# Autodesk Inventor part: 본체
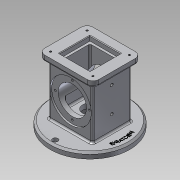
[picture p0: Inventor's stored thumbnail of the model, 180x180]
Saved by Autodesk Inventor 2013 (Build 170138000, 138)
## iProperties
Created: 2019-08
Part Number: 본체
Material: 알루미늄 6061
Document SubType Name: Modeling
Designer: hana-max10
Density: 2.40731 g/cm^3
Mass: 926.229 g
Surface Area: 783.577 cm^2
Volume: 384.757 cm^3
Author: hana-max10
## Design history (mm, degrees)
sketch "스케치1"
  geometry: C1 r 67.5 at (0, 0); 1 further point
  constraints: 1 centre point, 1 coincident
  dimensions: "d0" = 135 diameter of C1
extrude "돌출1" new body sketch "스케치1" distance "d2" = 10; taper "d3" = 0 deg
chamfer "모따기1" distance "d4" = 3; stored, may be unused: second distance "d5" = 2, angle "d6" = 45 deg
sketch "스케치2"
  geometry: C1 r 64.5 at (0, 0) reference; C2 r 4.5 at (0, 59); C3 r 4.5 at (-59, 0); C4 r 4.5 at (0, -59); A1 r 59 centre (0, 0) between (0, 59) and (-59, 0)
  constraints: 4 centre point, 3 point on circle, 2 vertical alignment, 1 coincident, 1 horizontal alignment
  dimensions: "d7" = 118 diameter of A1; "d9" = 9 diameter of C2; "d10" = 9 diameter of C3; "d11" = 9 diameter of C4
extrude "돌출2" cut sketch "스케치2" stored distance "d12" = 10; taper "d13" = 0 deg
sketch "스케치3"
  geometry: L1 (37, -33)-(-37, -33); L2 (-37, -33)-(-37, 33); L3 (-37, 33)-(37, 33); L4 (37, 33)-(37, -33); L5 (37, -33)-(-37, 33); L6 (-37, -33)-(37, 33); C1 r 64.5 at (0, 0) reference
  constraints: 12 end point, 2 midpoint, 2 parallel, 1 horizontal, 1 perpendicular
  dimensions: "d14" = 66 distance of L3.end L1.start; "d16" = 74 distance of L2.end L3.end
extrude "돌출3" join sketch "스케치3" distance "d17" = 88; taper "d18" = 0 deg
sketch "스케치4"
  geometry: L1 (-46, 41)-(46, 41); L2 (46, 41)-(46, -41); L3 (46, -41)-(-46, -41); L4 (-46, -41)-(-46, 41); L5 (-46, 41)-(46, -41); L6 (46, 41)-(-46, -41); 1 further point
  constraints: 12 end point, 2 midpoint, 2 parallel, 1 horizontal, 1 perpendicular
  dimensions: "d19" = 82 distance of L1.end L2.end; "d21" = 92 distance of L1.start L1.end
extrude "돌출4" join sketch "스케치4" distance "d22" = 10; taper "d23" = 0 deg
fillet "모깎기1" dims "d24" = 10
sketch "스케치5"
  geometry: A1 r 10 centre (-36, -31) between (-46, -31) and (-36, -41) reference; A2 r 10 centre (36, -31) between (36, -41) and (46, -31) reference; A3 r 10 centre (36, 31) between (46, 31) and (36, 41) reference; A4 r 10 centre (-36, 31) between (-36, 41) and (-46, 31) reference; 1 further point
hole "구멍1" sketch "스케치5" at (36, 31), (-36, 31), (-36, -31), (36, -31) diameter "d25" = 3.242; stored, may be unused: countersink angle "d29" = 90 deg, drill point angle "d31" = 118 deg; dims "d26" = 4, "d27" = 4, "d28" = 2, "d30" = 6
sketch "스케치6"
  geometry: L1 (-26, 26)-(26, 26); L2 (26, 26)-(26, -26); L3 (26, -26)-(-26, -26); L4 (-26, -26)-(-26, 26); L5 (-26, 26)-(26, -26); L6 (26, 26)-(-26, -26); 1 further point
  constraints: 12 end point, 2 midpoint, 2 parallel, 1 horizontal, 1 perpendicular
  dimensions: "d32" = 52 distance of L1.end L2.end; "d34" = 52 distance of L2.end L3.end
extrude "돌출5" cut sketch "스케치6" distance "d35" = 8; taper "d36" = 0 deg
sketch "스케치7"
  geometry: C1 r 67.5 at (0, 0) reference; C2 r 25 at (0, 0)
  constraints: 1 centre point, 1 coincident
  dimensions: "d37" = 50 diameter of C2
extrude "돌출6" cut sketch "스케치7" distance "d39" = 18; taper "d40" = 0 deg
sketch "스케치8"
  geometry: L1 (-30.5, -10)-(104.5, -10) reference; C1 r 35 at (37, 44); 2 further points
  constraints: 1 centre point, 1 midpoint, 1 vertical alignment
  dimensions: "d41" = 54 distance from line of L1 C1.centre; "d42" = 70 diameter of C1
extrude "돌출7" cut sketch "스케치8" distance "d43" = 3; taper "d44" = 0 deg
sketch "스케치9"
  geometry: L1 (-22, 22)-(22, 22); L2 (22, 22)-(22, -22); L3 (22, -22)-(-22, -22); L4 (-22, -22)-(-22, 22); L5 (-22, 22)-(22, -22); L6 (22, 22)-(-22, -22); 1 further point
  constraints: 12 end point, 2 midpoint, 2 parallel, 1 horizontal, 1 perpendicular
  dimensions: "d45" = 44 distance of L2.end L3.end; "d47" = 44 distance of L1.end L2.end
extrude "돌출8" cut sketch "스케치9" distance "d48" = 74; taper "d49" = 0 deg
fillet "모깎기2" dims "d50" = 3
sketch "스케치10"
  geometry: C1 r 35 at (0, 0) reference; C2 r 24 at (0, 0); 1 further point
  constraints: 1 centre point, 1 coincident
  dimensions: "d51" = 48 diameter of C2
extrude "돌출9" cut sketch "스케치10" stored distance "d53" = 74; taper "d54" = 0 deg
sketch "스케치11" dims "d55" = 58
  geometry: C1 r 24 at (0, 0) reference; C2 r 35 at (0, 0) reference; 3 further points
  constraints: 2 vertical alignment, 1 coincident, 2 other
hole "구멍2" sketch "스케치11" at (0, 29) diameter "d57" = 3.242; stored, may be unused: countersink angle "d61" = 90 deg, drill point angle "d63" = 118 deg; dims "d58" = 4, "d59" = 4, "d60" = 2, "d62" = 6
sketch "스케치12"
  geometry: C1 r 25 at (0, 0) reference; C2 r 12.5 at (0, 0)
  constraints: 1 centre point, 1 coincident
  dimensions: "d67" = 25 diameter of C2
extrude "돌출10" cut sketch "스케치12" stored distance "d69" = 74; taper "d70" = 0 deg
sketch "스케치13"
  geometry: L1 (10, -34.5)-(10, 100.5) reference; 2 further points
  constraints: 1 horizontal alignment
  dimensions: "d71" = 37 distance from line of point (-27, 33) L1
hole "구멍3" sketch "스케치13" at (-27, 33) diameter "d72" = 4.917; stored, may be unused: countersink angle "d76" = 90 deg, drill point angle "d78" = 0 deg; dims "d73" = 4, "d74" = 4, "d75" = 2, "d77" = 6
sketch "스케치14"
  geometry: C1 r 2.458 at (-27, 33) reference; 2 further points
  constraints: 1 horizontal alignment
  dimensions: "d79" = 43 distance of C1.centre point (-70, 33)
hole "구멍4" sketch "스케치14" at (-70, 33) diameter "d80" = 4.917; stored, may be unused: countersink angle "d84" = 90 deg, drill point angle "d86" = 0 deg; dims "d81" = 4, "d82" = 4, "d83" = 2, "d85" = 15
chamfer "모따기2" distance "d87" = 1; stored, may be unused: second distance "d88" = 2, angle "d89" = 45 deg
fillet "모깎기3" dims "d90" = 3
fillet "모깎기4" dims "d91" = 3
fillet "모깎기5" dims "d92" = 3
fillet "모깎기6" dims "d93" = 3
fillet "모깎기7" dims "d94" = 3
fillet "모깎기8" dims "d95" = 3
node "작업 평면1"
sketch "스케치15"
  geometry: C1 r 59 at (0, 0); 1 further point
  constraints: 1 centre point, 1 coincident, 1 other
  dimensions: "d97" = 118 diameter of C1
feature "엠보싱1" sketch "스케치15" dims "d14" = 66, "d16" = 74, "d99" = 0.5, "d100" = 0
node "솔리드1"
mirror "대칭1"
pattern_circular "원형 패턴1" dims angle "d65" = 360 deg
mirror "대칭2"
other parameters: "d96" = 241.75
